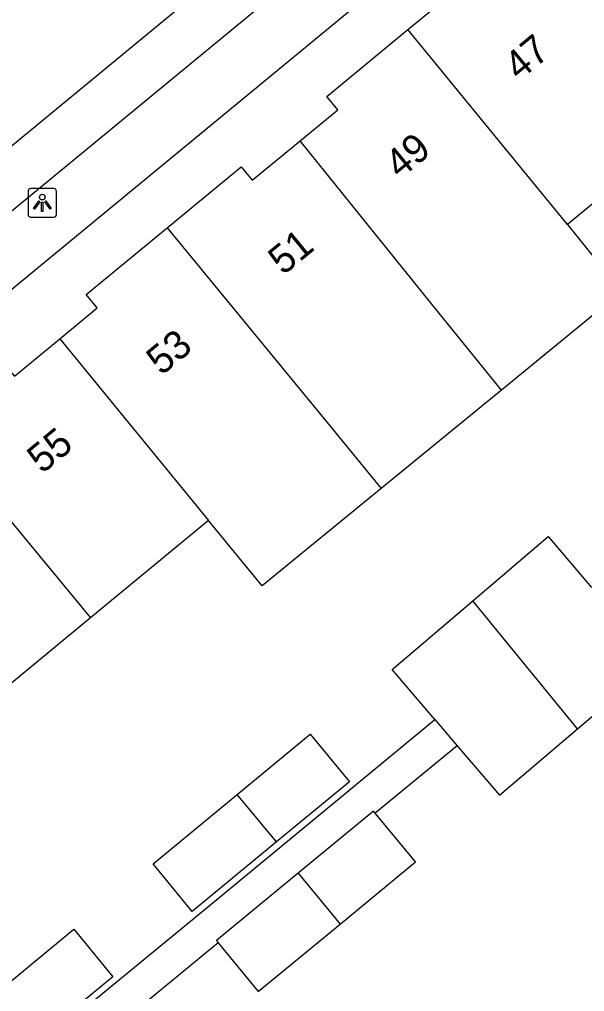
# Model space of a CAD drawing. Extents: x 161771 to 163125, y 382479 to 383177.
# Drawn here: x 161976.75 to 161996.56, y 382999.19 to 383033.26 of the extents above; entities that cross this region are included whole.
import ezdxf

# ---------------------------------------------------------------- set-up
doc = ezdxf.new("R2010")
doc.units = 0
for name, color, linetype in [('IMGEO_Lichtpunt', 7, 'Continuous'), ('IMGEO_Pand', 7, 'Continuous'), ('IMGEO_Pand_nummerreeks', 7, 'Continuous'), ('IMGEO_Rijbaan_lokaal_open', 7, 'Continuous'), ('IMGEO_Voetpad_open', 7, 'Continuous')]:
    doc.layers.add(name, color=color, linetype=linetype)

msp = doc.modelspace()

# ---------------------------------------------------------------- linework, layer by layer
at = {"layer": 'IMGEO_Lichtpunt'}
for p, q in [((161977.954, 383027.332), (161977.146, 383027.332)), ((161977.954, 383027.332), (161977.146, 383027.332)), ((161977.052, 383027.237), (161977.052, 383026.43)), ((161977.052, 383027.237), (161977.052, 383026.43)), ((161978.048, 383026.43), (161978.048, 383027.237)), ((161978.048, 383026.43), (161978.048, 383027.237)), ((161977.146, 383026.336), (161977.954, 383026.336)), ((161977.146, 383026.336), (161977.954, 383026.336))]:
    msp.add_line(p, q, dxfattribs=at)
for points in [[(161977.426, 383026.901), (161977.465, 383026.873), (161977.277, 383026.611), (161977.239, 383026.638), (161977.426, 383026.901)], [(161977.528, 383026.853), (161977.575, 383026.853), (161977.575, 383026.531), (161977.528, 383026.531), (161977.528, 383026.853)], [(161977.638, 383026.873), (161977.676, 383026.9), (161977.863, 383026.638), (161977.824, 383026.61), (161977.638, 383026.873)]]:
    msp.add_lwpolyline(points, dxfattribs=at)
msp.add_circle((161977.551, 383027.035), 0.0994, dxfattribs=at)
for centre, start, end in [((161977.146, 383027.237), 90, 180), ((161977.146, 383027.237), 90, 180), ((161977.954, 383027.237), 0, 90), ((161977.954, 383027.237), 0, 90), ((161977.146, 383026.43), 180, 270), ((161977.146, 383026.43), 180, 270), ((161977.954, 383026.43), 270, 0), ((161977.954, 383026.43), 270, 360)]:
    msp.add_arc(centre, 0.0946, start, end, dxfattribs=at)
at = {"layer": 'IMGEO_Pand'}
for points in [[(161990.371, 383032.908), (161992.952, 383035.03), (161993.337, 383034.57), (161994.916, 383035.869)], [(161986.59, 383029.007), (161987.912, 383030.096), (161987.524, 383030.566), (161990.371, 383032.908)], [(161995.966, 383026.074), (161990.371, 383032.908)], [(162000, 383029.399), (161995.966, 383026.074)], [(161981.933, 383025.962), (161984.526, 383028.098), (161984.909, 383027.624), (161986.59, 383029.007)], [(161993.649, 383020.27), (161991.76, 383022.608), (161991.457, 383022.983), (161986.59, 383029.007)], [(161978.169, 383022.07), (161979.48, 383023.151), (161979.091, 383023.621), (161981.933, 383025.962)], [(161981.933, 383025.962), (161987.539, 383019.128), (161989.429, 383016.818)], [(161995.966, 383026.074), (161997.857, 383023.712), (161993.649, 383020.27)], [(161973.604, 383019.1), (161976.175, 383021.217), (161976.572, 383020.753), (161978.169, 383022.07)], [(161978.169, 383022.07), (161983.38, 383015.701)], [(161993.649, 383020.27), (161989.429, 383016.818)], [(161973.604, 383019.1), (161979.244, 383012.292)], [(161989.429, 383016.818), (161985.258, 383013.406), (161983.38, 383015.701)], [(161983.38, 383015.701), (161979.244, 383012.292)], [(161992.645, 383012.884), (161995.29, 383015.137), (161996.811, 383013.351)], [(161991.319, 383008.72), (161989.82, 383010.48), (161992.645, 383012.884)], [(161996.318, 383008.395), (161992.645, 383012.884)], [(161979.244, 383012.292), (161975.045, 383008.831)], [(161996.318, 383008.395), (161999.05, 383010.721), (161997.585, 383012.442)], [(161991.319, 383008.72), (161992.098, 383007.804)], [(161984.382, 383006.09), (161986.947, 383008.205), (161988.319, 383006.54), (161985.758, 383004.429)], [(161992.098, 383007.804), (161993.58, 383006.064), (161996.318, 383008.395)], [(161985.758, 383004.429), (161982.808, 383001.997), (161981.436, 383003.662), (161984.382, 383006.09)], [(161985.758, 383004.429), (161984.382, 383006.09)], [(161989.228, 383005.438), (161989.166, 383005.513), (161986.522, 383003.334)], [(161987.992, 383001.551), (161990.636, 383003.73), (161989.228, 383005.438)], [(161986.522, 383003.334), (161983.654, 383000.97), (161983.716, 383000.895)], [(161986.522, 383003.334), (161987.992, 383001.551)], [(161976.002, 382999.183), (161978.654, 383001.368), (161980.026, 382999.704), (161977.374, 382997.519)], [(161983.716, 383000.895), (161985.124, 382999.187), (161987.992, 383001.551)]]:
    msp.add_lwpolyline(points, dxfattribs=at)
at = {"layer": 'IMGEO_Rijbaan_lokaal_open'}
msp.add_lwpolyline([(161954.449, 383010.709), (161958.818, 383014.267), (161963.107, 383017.828), (161972.581, 383025.628), (161988.094, 383038.411), (162000, 383048.208), (162014.364, 383060.022)], dxfattribs=at)
at = {"layer": 'IMGEO_Voetpad_open'}
for points in [[(161956.028, 383001.349), (161954.345, 383005.756), (161958.418, 383008.932), (162000, 383043.194), (162019.717, 383059.44)], [(162013.207, 383056.799), (162000, 383045.919), (161963.694, 383016.025), (161957.739, 383011.105)], [(161964.215, 382986.434), (161983.402, 383002.194), (161991.319, 383008.72)], [(161992.098, 383007.804), (161989.228, 383005.438)], [(161983.716, 383000.895), (161980.934, 382998.602)]]:
    msp.add_lwpolyline(points, dxfattribs=at)

# ---------------------------------------------------------------- texts
at = {"layer": 'IMGEO_Pand_nummerreeks'}
for s, rotation, p in [('47', 39.4791, (161994.272, 383031.089)), ('49', 39.4768, (161990.092, 383027.645)), ('51', 39.4768, (161985.998, 383024.272)), ('53', 39.4791, (161981.727, 383020.756)), ('55', 39.4791, (161977.546, 383017.311))]:
    msp.add_text(s, height=1, rotation=rotation, dxfattribs=at).set_placement(p)

doc.saveas('drawing.dxf')
